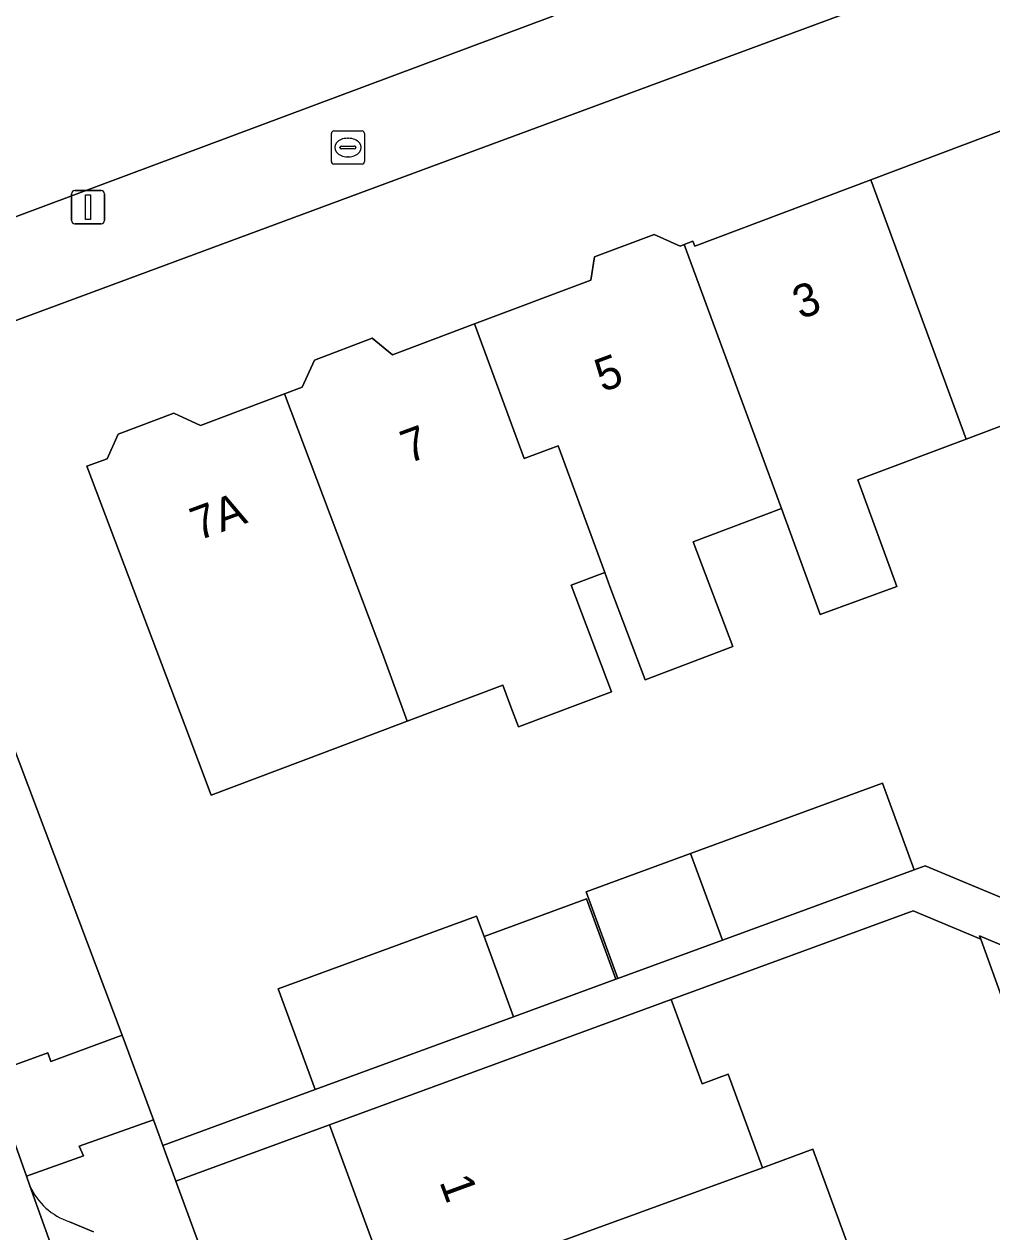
# Model space of a CAD drawing. Extents: x 161258 to 161838, y 380833 to 381727.
# Drawn here: x 161708.22 to 161737.48, y 381465.11 to 381501.62 of the extents above; entities that cross this region are included whole.
import ezdxf

# ---------------------------------------------------------------- set-up
doc = ezdxf.new("R2010")
doc.units = 0
for name, color, linetype in [('IMGEO_Brandkraan', 7, 'Continuous'), ('IMGEO_Erf', 7, 'Continuous'), ('IMGEO_Lichtmast', 7, 'Continuous'), ('IMGEO_Pand', 7, 'Continuous'), ('IMGEO_Pand_nummerreeks', 7, 'Continuous'), ('IMGEO_Parkeervlak_open', 7, 'Continuous'), ('IMGEO_Rijbaan_lokaal_open', 7, 'Continuous'), ('IMGEO_Voetpad_open', 7, 'Continuous')]:
    doc.layers.add(name, color=color, linetype=linetype)

msp = doc.modelspace()

# ---------------------------------------------------------------- linework, layer by layer
at = {"layer": 'IMGEO_Brandkraan'}
for p, q in [((161717.512, 381497.464), (161717.512, 381498.316)), ((161717.587, 381498.39), (161718.439, 381498.39)), ((161718.513, 381498.316), (161718.513, 381497.464)), ((161717.771, 381497.884), (161717.771, 381497.896)), ((161717.814, 381497.933), (161718.212, 381497.933)), ((161718, 381498.17), (161718.025, 381498.17)), ((161718.255, 381497.896), (161718.255, 381497.884)), ((161718.209, 381497.847), (161717.811, 381497.847)), ((161718.023, 381497.61), (161717.998, 381497.61)), ((161718.439, 381497.39), (161717.587, 381497.39))]:
    msp.add_line(p, q, dxfattribs=at)
for points in [[(161717.512, 381497.464), (161717.512, 381498.316)], [(161717.587, 381498.39), (161718.439, 381498.39)], [(161718.513, 381498.316), (161718.513, 381497.464)], [(161718.439, 381497.39), (161717.587, 381497.39)]]:
    msp.add_lwpolyline(points, dxfattribs=at)
for centre, radius, start, end in [((161717.589, 381498.314), 0.0765, 91.552, 178.448), ((161717.589, 381498.314), 0.0765, 91.552, 178.448), ((161718.437, 381498.314), 0.0765, 1.552, 88.448), ((161718.437, 381498.314), 0.0765, 1.552, 88.448), ((161717.811, 381497.893), 0.0403, 85.8775, 175.7526), ((161717.808, 381497.883), 0.0366, 178.938, 274.7102), ((161718.212, 381497.89), 0.043, 264.8664, 352.4533), ((161718.216, 381497.895), 0.0386, 1.7309, 96.639), ((161717.589, 381497.466), 0.0765, 181.552, 268.448), ((161717.589, 381497.466), 0.0765, 181.552, 268.448), ((161718.437, 381497.466), 0.0765, 271.552, 358.448), ((161718.437, 381497.466), 0.0765, 271.552, 358.448)]:
    msp.add_arc(centre, radius, start, end, dxfattribs=at)
for centre, major_axis, ratio, start_param, end_param in [((161717.999, 381497.89), (-0.387, 0.002), 0.722429, 4.712389, 7.853982), ((161718.024, 381497.89), (-0.39, 0.002), 0.717154, 1.570796, 4.712389)]:
    msp.add_ellipse(centre, major_axis=major_axis, ratio=ratio, start_param=start_param, end_param=end_param, dxfattribs=at)
at = {"layer": 'IMGEO_Erf'}
for points in [[(161733.594, 381502.147), (161727.792, 381500), (161721.654, 381497.729), (161703.642, 381491.064), (161711.187, 381471.057), (161712.129, 381468.494), (161712.412, 381467.723), (161717.016, 381469.415), (161715.9, 381472.459), (161721.898, 381474.657), (161722.125, 381474.039), (161725.219, 381475.174), (161726.108, 381472.747), (161726.174, 381472.774), (161725.214, 381475.391), (161728.371, 381476.549), (161734.167, 381478.674), (161735.127, 381476.056), (161735.459, 381476.18), (161742.758, 381473.134)], [(161742.73, 381491.352), (161736.7, 381489.079), (161733.423, 381487.844), (161734.606, 381484.625), (161732.29, 381483.773), (161731.114, 381486.973), (161728.452, 381485.97), (161729.647, 381482.802), (161726.996, 381481.802), (161725.932, 381484.623), (161725.773, 381485.046), (161724.761, 381484.665), (161725.978, 381481.435), (161723.171, 381480.377), (161722.941, 381480.986), (161722.726, 381481.558), (161722.697, 381481.634), (161719.806, 381480.544), (161717.276, 381479.59), (161713.876, 381478.308), (161713.078, 381480.425), (161710.123, 381488.262), (161710.729, 381488.479), (161711.068, 381489.227), (161712.744, 381489.859), (161713.558, 381489.49), (161716.094, 381490.447), (161716.625, 381490.647), (161716.996, 381491.467), (161718.746, 381492.126), (161719.361, 381491.622), (161721.842, 381492.557), (161725.354, 381493.881), (161725.469, 381494.583), (161727.272, 381495.263), (161728.051, 381494.91), (161728.179, 381494.958), (161728.442, 381495.057), (161728.497, 381494.909), (161733.82, 381496.915), (161739.465, 381499.043)], [(161738.57, 381470.014), (161737.144, 381473.959), (161735.098, 381474.813), (161727.787, 381472.135), (161728.72, 381469.59), (161729.505, 381469.878), (161730.54, 381467.051), (161732.063, 381467.606), (161734.046, 381462.193), (161733.027, 381461.82), (161730.506, 381460.896), (161731.586, 381457.948), (161732.749, 381458.374), (161733.581, 381456.102), (161732.452, 381455.688), (161733.568, 381452.64), (161734.69, 381453.051), (161735.563, 381450.667), (161735.609, 381450.542), (161739.215, 381451.864)], [(161740.346, 381448.778), (161737.465, 381447.722), (161738.967, 381443.62), (161735.595, 381442.384), (161731.131, 381440.748), (161730.632, 381442.111), (161727.489, 381440.959), (161727.31, 381441.447), (161726.747, 381441.241), (161725.715, 381444.058), (161726.278, 381444.264), (161725.309, 381446.909), (161723.319, 381452.34), (161721.406, 381457.561), (161719.415, 381462.994), (161717.453, 381468.348), (161712.809, 381466.642), (161722.039, 381441.525), (161722.379, 381440.599), (161722.102, 381438)]]:
    msp.add_lwpolyline(points, dxfattribs=at)
at = {"layer": 'IMGEO_Lichtmast'}
for p, q in [((161709.658, 381495.688), (161709.658, 381496.488)), ((161709.658, 381496.488), (161709.658, 381495.688)), ((161709.758, 381496.588), (161710.548, 381496.588)), ((161710.548, 381496.588), (161709.758, 381496.588)), ((161710.648, 381496.488), (161710.648, 381495.688)), ((161710.648, 381495.688), (161710.648, 381496.488)), ((161710.548, 381495.588), (161709.758, 381495.588)), ((161709.758, 381495.588), (161710.548, 381495.588))]:
    msp.add_line(p, q, dxfattribs=at)
msp.add_lwpolyline([(161710.078, 381496.463), (161710.228, 381496.463), (161710.228, 381495.713), (161710.078, 381495.713), (161710.078, 381496.463)], dxfattribs=at)
for centre, start, end in [((161709.758, 381496.488), 90, 180), ((161709.758, 381496.488), 90, 180), ((161710.548, 381496.488), 0, 90), ((161710.548, 381496.488), 360, 90), ((161709.758, 381495.688), 180, 270), ((161709.758, 381495.688), 180, 270), ((161710.548, 381495.688), 270, 0), ((161710.548, 381495.688), 270, 0)]:
    msp.add_arc(centre, 0.1, start, end, dxfattribs=at)
at = {"layer": 'IMGEO_Pand'}
for points in [[(161733.82, 381496.915), (161736.7, 381489.079), (161742.73, 381491.352), (161741.758, 381493.931), (161739.995, 381498.609), (161739.465, 381499.043)], [(161733.82, 381496.915), (161728.497, 381494.909), (161728.442, 381495.057), (161728.179, 381494.958), (161731.114, 381486.973), (161732.29, 381483.773), (161734.606, 381484.625), (161733.423, 381487.844), (161736.7, 381489.079)], [(161725.773, 381485.046), (161725.932, 381484.623), (161726.996, 381481.802), (161729.647, 381482.802), (161728.452, 381485.97), (161731.114, 381486.973), (161728.179, 381494.958), (161728.051, 381494.91), (161727.272, 381495.263), (161725.469, 381494.583), (161725.354, 381493.881), (161721.842, 381492.557), (161723.336, 381488.491), (161724.371, 381488.871)], [(161724.371, 381488.871), (161723.336, 381488.491), (161721.842, 381492.557), (161719.361, 381491.622), (161718.746, 381492.126), (161716.996, 381491.467), (161716.625, 381490.647), (161716.094, 381490.447), (161719.053, 381482.593), (161719.806, 381480.544), (161722.697, 381481.634), (161722.726, 381481.558), (161722.941, 381480.986), (161723.171, 381480.377), (161725.978, 381481.435), (161724.761, 381484.665), (161725.773, 381485.046)], [(161719.053, 381482.593), (161716.094, 381490.447), (161713.558, 381489.49), (161712.744, 381489.859), (161711.068, 381489.227), (161710.729, 381488.479), (161710.123, 381488.262), (161713.078, 381480.425), (161713.876, 381478.308), (161717.276, 381479.59), (161719.806, 381480.544)], [(161729.333, 381473.932), (161735.127, 381476.056), (161734.167, 381478.674), (161728.371, 381476.549)], [(161729.333, 381473.932), (161728.371, 381476.549), (161725.214, 381475.391), (161726.174, 381472.774)], [(161722.125, 381474.039), (161723.013, 381471.613), (161726.108, 381472.747), (161725.219, 381475.174)], [(161722.125, 381474.039), (161721.898, 381474.657), (161715.9, 381472.459), (161717.016, 381469.415), (161723.013, 381471.613)], [(161737.109, 381474.056), (161737.144, 381473.959), (161738.57, 381470.014), (161738.718, 381470.069), (161741.924, 381471.25), (161741.582, 381472.179)], [(161728.72, 381469.59), (161727.787, 381472.135), (161722.096, 381470.05), (161717.453, 381468.348), (161719.415, 381462.994), (161730.54, 381467.051), (161729.505, 381469.878)], [(161730.54, 381467.051), (161719.415, 381462.994), (161721.406, 381457.561), (161730.506, 381460.896), (161733.027, 381461.82), (161734.046, 381462.193), (161732.063, 381467.606)]]:
    msp.add_lwpolyline(points, close=True, dxfattribs=at)
at = {"layer": 'IMGEO_Parkeervlak_open'}
for points in [[(161708.399, 381466.5), (161712.064, 381456.269), (161713.482, 381452.388), (161714.435, 381449.777), (161716.781, 381443.354), (161717.213, 381442.272)], [(161710.318, 381465.111), (161709.596, 381465.418)]]:
    msp.add_lwpolyline(points, dxfattribs=at)
msp.add_arc((161710.205, 381467.295), 1.974, 203.7634, 252.014, dxfattribs=at)
at = {"layer": 'IMGEO_Rijbaan_lokaal_open'}
for points in [[(161725.523, 381508.66), (161693.452, 381496.782), (161671.265, 381488.572), (161658.225, 381483.74), (161660.386, 381478.179), (161666.398, 381480.402), (161670.065, 381481.78), (161673.091, 381482.875), (161690.547, 381489.321), (161692.364, 381489.984), (161692.335, 381490.062), (161701.588, 381493.419), (161724.209, 381501.861)], [(161696.56, 381488.313), (161696.636, 381488.131), (161698.582, 381482.625), (161703.946, 381468.421), (161705.542, 381463.901), (161705.655, 381463.593), (161708.698, 381455.271), (161710.194, 381451.196), (161713.482, 381452.388), (161712.064, 381456.269), (161708.399, 381466.5), (161708.292, 381466.799), (161707.19, 381469.886), (161707.125, 381470.068), (161707.048, 381470.326), (161703.495, 381479.945), (161699.851, 381489.581)]]:
    msp.add_lwpolyline(points, dxfattribs=at)
at = {"layer": 'IMGEO_Voetpad_open'}
for points in [[(161729.353, 381503.742), (161729.019, 381503.62), (161724.209, 381501.861), (161701.588, 381493.419)], [(161699.837, 381489.622), (161703.642, 381491.064), (161721.654, 381497.729), (161727.792, 381500), (161733.594, 381502.147)], [(161707.048, 381470.326), (161707.125, 381470.068), (161707.19, 381469.886), (161708.943, 381470.523), (161709.031, 381470.257), (161711.187, 381471.057), (161703.642, 381491.064)], [(161712.809, 381466.642), (161712.412, 381467.723), (161712.129, 381468.494), (161709.884, 381467.702), (161710.022, 381467.409), (161708.292, 381466.799), (161708.399, 381466.5)], [(161717.622, 381440.68), (161718.768, 381441.075), (161718.855, 381440.706), (161719.872, 381441.096), (161719.985, 381440.791), (161722.039, 381441.525), (161712.809, 381466.642)], [(161709.596, 381465.418), (161710.318, 381465.111)]]:
    msp.add_lwpolyline(points, dxfattribs=at)
for points in [[(161742.758, 381473.134), (161735.459, 381476.18), (161735.127, 381476.056), (161729.333, 381473.932), (161726.174, 381472.774), (161726.108, 381472.747), (161723.013, 381471.613), (161717.016, 381469.415), (161712.412, 381467.723), (161712.809, 381466.642), (161717.453, 381468.348), (161722.096, 381470.05), (161727.787, 381472.135), (161735.098, 381474.813), (161737.144, 381473.959), (161737.109, 381474.056), (161741.582, 381472.179), (161741.924, 381471.25), (161742.966, 381468.422), (161744.914, 381463.132), (161744.794, 381463.088), (161745.725, 381460.557), (161746.063, 381460.681), (161747.274, 381461.127)], [(161711.187, 381471.057), (161709.031, 381470.257), (161708.943, 381470.523), (161707.19, 381469.886), (161708.292, 381466.799), (161710.022, 381467.409), (161709.884, 381467.702), (161712.129, 381468.494)]]:
    msp.add_lwpolyline(points, close=True, dxfattribs=at)
msp.add_arc((161710.205, 381467.295), 1.974, 203.7634, 252.014, dxfattribs=at)

# ---------------------------------------------------------------- texts
at = {"layer": 'IMGEO_Pand_nummerreeks'}
for s, rotation, p in [('3', 20.2132, (161731.689, 381492.687)), ('5', 20.2132, (161725.707, 381490.485)), ('7', 20.1624, (161719.84, 381488.329)), ('7A', 20.0967, (161713.48, 381485.998)), ('1', 290.1221, (161720.768, 381466.628))]:
    msp.add_text(s, height=1, rotation=rotation, dxfattribs=at).set_placement(p)

doc.saveas('drawing.dxf')
